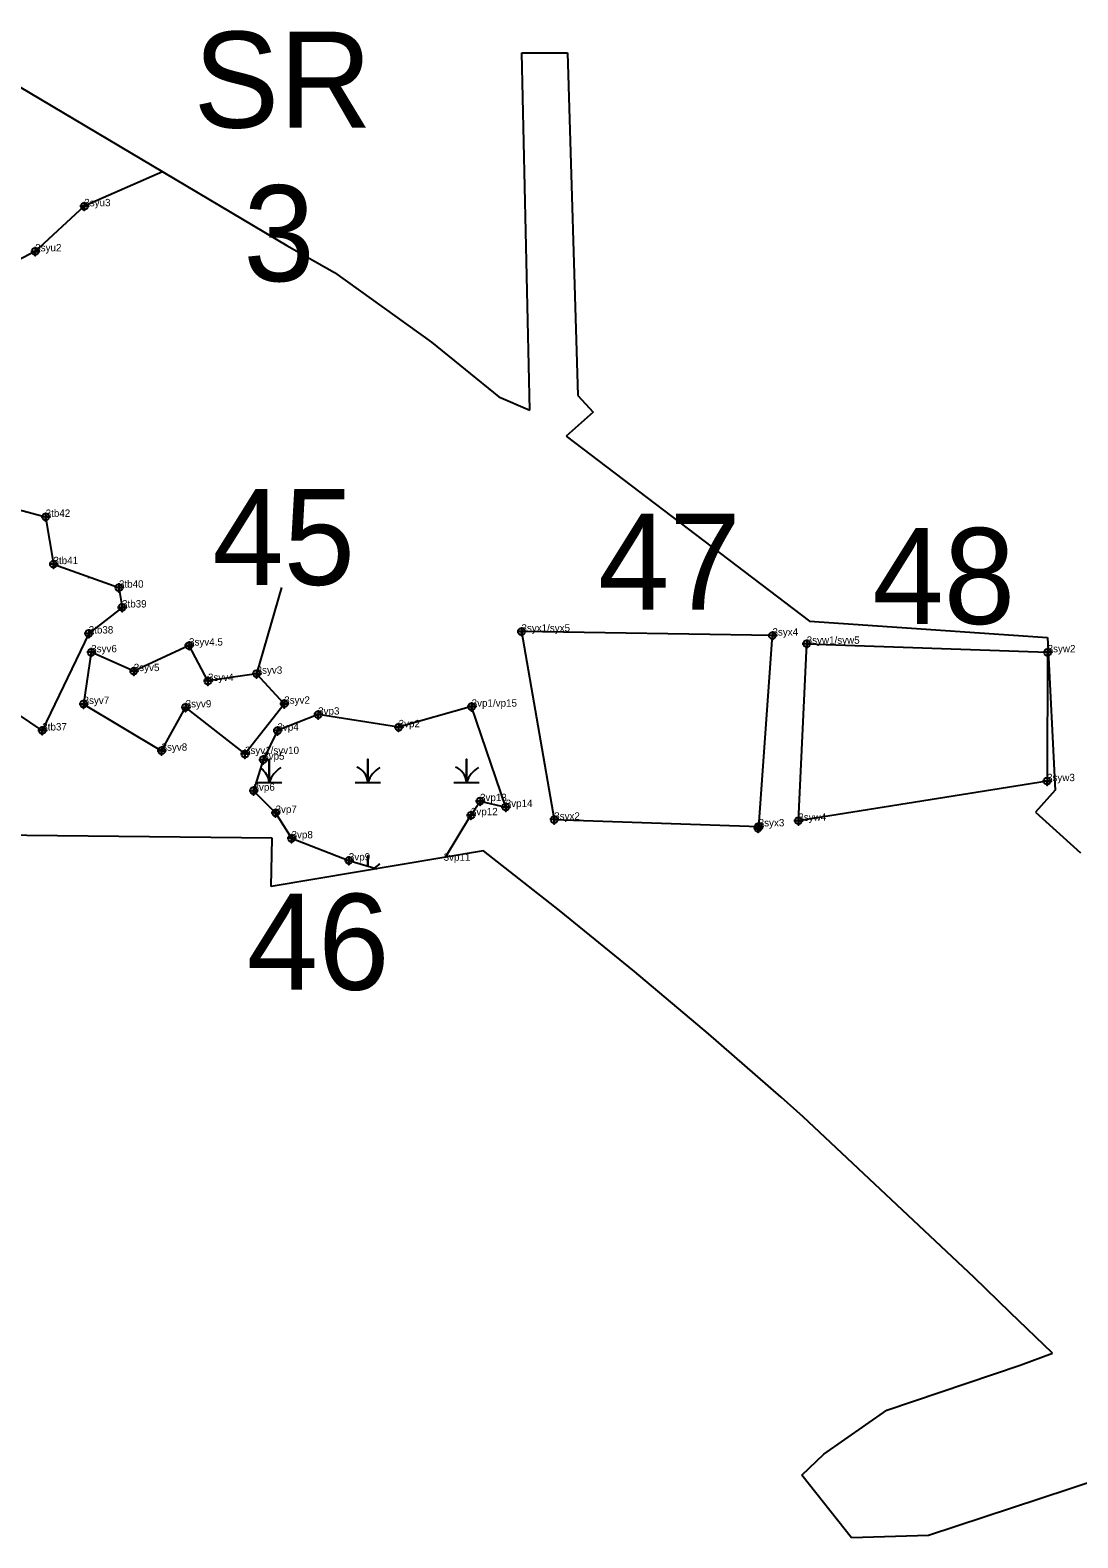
# Model space of a CAD drawing. Extents: x 2071991 to 2268989, y 436479 to 469629.
# Drawn here: x 2109076 to 2109789, y 454920 to 455947 of the extents above; entities that cross this region are included whole.
import ezdxf

# ---------------------------------------------------------------- set-up
doc = ezdxf.new("R2010")
doc.units = 0
for name, color, linetype in [('approx_PSA', 7, 'Continuous'), ('Default', 7, 'Continuous'), ('Exist Environmental Wetland Boundary', 7, 'Continuous'), ('Exist Environmental Wetland Boundary Cogo Comment', 7, 'Continuous'), ('Exist Environmental Wetland Boundary Cogo Point CELL', 7, 'Continuous'), ('Exist Hydro Jurisdictional Stream or Body of Water NEU Mitigable', 7, 'Continuous'), ('Exist Hydro Jurisdictional Stream or Body of Water NEU Mitigable Cogo Comment', 7, 'Continuous'), ('Exist Hydro Jurisdictional Stream or Body of Water NEU Mitigable Cogo Point CELL', 7, 'Continuous'), ('Exist Hydro Jurisdictional Stream or Body of Water NEU NonMitigable', 7, 'Continuous'), ('Exist Hydro Jurisdictional Stream or Body of Water NEU NonMitigable Cogo Comment', 7, 'Continuous'), ('Exist Hydro Jurisdictional Stream or Body of Water NEU NonMitigable Cogo Point CELL', 7, 'Continuous'), ('Exist Hydro Swamp or Marsh', 7, 'Continuous')]:
    doc.layers.add(name, color=color, linetype=linetype)

msp = doc.modelspace()

# ---------------------------------------------------------------- linework, layer by layer
at = {"layer": 'approx_PSA'}
for p, q in [((2109415.7, 455688), (2109410.3, 455931.3)), ((2109410.3, 455931.3), (2109441.4, 455931.3)), ((2109441.4, 455931.3), (2109448.3, 455697.9)), ((2109049.7, 455919.1), (2109250.2, 455800)), ((2109250.2, 455800), (2109282.8, 455781.7)), ((2109282.8, 455781.7), (2109348.8, 455734.4)), ((2109348.8, 455734.4), (2109394.7, 455697.1)), ((2109448.3, 455697.9), (2109458.8, 455686.6)), ((2109394.7, 455697.1), (2109415.7, 455688)), ((2109458.8, 455686.6), (2109440.4, 455670.3)), ((2109440.4, 455670.3), (2109606.1, 455544.3)), ((2109606.1, 455544.3), (2109768.1, 455533.3)), ((2109768.1, 455533.3), (2109773.3, 455429.3)), ((2109773.3, 455429.3), (2109760, 455414.3)), ((2109760, 455414.3), (2109790.7, 455386.8)), ((2109240.3, 455396.7), (2108999.5, 455399.4)), ((2109239.7, 455363.8), (2109240.3, 455396.7)), ((2109384.1, 455388.1), (2109239.7, 455363.8)), ((2109435.9, 455347.5), (2109384.1, 455388.1)), ((2109486.9, 455306), (2109435.9, 455347.5)), ((2109537.3, 455263.6), (2109486.9, 455306)), ((2109586.9, 455220.4), (2109537.3, 455263.6)), ((2109601.7, 455207), (2109586.9, 455220.4)), ((2109718.2, 455097.6), (2109601.7, 455207)), ((2109742.7, 455073.9), (2109718.2, 455097.6)), ((2109771.5, 455046.1), (2109742.7, 455073.9)), ((2109749.6, 455038), (2109771.5, 455046.1)), ((2109658.7, 455007.4), (2109749.6, 455038)), ((2109615.9, 454977.5), (2109658.7, 455007.4)), ((2109600.8, 454963.2), (2109615.9, 454977.5)), ((2109634.8, 454920.5), (2109600.8, 454963.2)), ((2109805.6, 454961.2), (2109762.9, 454947.1)), ((2109762.9, 454947.1), (2109687, 454922)), ((2109687, 454922), (2109634.8, 454920.5))]:
    msp.add_line(p, q, dxfattribs=at)
at = {"layer": 'Default'}
msp.add_line((2109246.6, 455567.3), (2109229.7, 455508.6), dxfattribs=at)
at = {"layer": 'Exist Environmental Wetland Boundary'}
for points in [[(2109058, 455622.8), (2109086.1, 455615.4), (2109091.4, 455583.2), (2109136, 455567.2), (2109138.1, 455553.7), (2109115.4, 455536), (2109083.8, 455470), (2109058.6, 455486.9)], [(2109358.4, 455383.8), (2109375.6, 455412.3), (2109381.8, 455421.9), (2109399.3, 455417.9), (2109376.1, 455486.2), (2109326.4, 455472.2), (2109271.6, 455480.8), (2109243.9, 455469.9), (2109234.2, 455450.1), (2109227.6, 455429), (2109242.6, 455413.9), (2109253.5, 455396.6), (2109292.5, 455381.5), (2109311.8, 455375.9)]]:
    msp.add_lwpolyline(points, dxfattribs=at)
at = {"layer": 'Exist Environmental Wetland Boundary Cogo Point CELL'}
for points in [[(2109086.1, 455618.4), (2109086.1, 455612.4), (2109086.1, 455615.4), (2109089.1, 455615.4), (2109083.1, 455615.4)], [(2109091.4, 455586.2), (2109091.4, 455580.2), (2109091.4, 455583.2), (2109094.4, 455583.2), (2109088.4, 455583.2)], [(2109136, 455570.2), (2109136, 455564.2), (2109136, 455567.2), (2109139, 455567.2), (2109133, 455567.2)], [(2109138.1, 455556.7), (2109138.1, 455550.7), (2109138.1, 455553.7), (2109141.1, 455553.7), (2109135.1, 455553.7)], [(2109115.4, 455539), (2109115.4, 455533), (2109115.4, 455536), (2109118.4, 455536), (2109112.4, 455536)], [(2109271.6, 455483.8), (2109271.6, 455477.8), (2109271.6, 455480.8), (2109274.6, 455480.8), (2109268.6, 455480.8)], [(2109376.1, 455489.2), (2109376.1, 455483.2), (2109376.1, 455486.2), (2109379.1, 455486.2), (2109373.1, 455486.2)], [(2109083.8, 455473), (2109083.8, 455467), (2109083.8, 455470), (2109086.8, 455470), (2109080.8, 455470)], [(2109243.9, 455472.9), (2109243.9, 455466.9), (2109243.9, 455469.9), (2109246.9, 455469.9), (2109240.9, 455469.9)], [(2109326.4, 455475.2), (2109326.4, 455469.2), (2109326.4, 455472.2), (2109329.4, 455472.2), (2109323.4, 455472.2)], [(2109234.2, 455453.1), (2109234.2, 455447.1), (2109234.2, 455450.1), (2109237.2, 455450.1), (2109231.2, 455450.1)], [(2109227.6, 455432), (2109227.6, 455426), (2109227.6, 455429), (2109230.6, 455429), (2109224.6, 455429)], [(2109381.8, 455424.9), (2109381.8, 455418.9), (2109381.8, 455421.9), (2109384.8, 455421.9), (2109378.8, 455421.9)], [(2109399.3, 455420.9), (2109399.3, 455414.9), (2109399.3, 455417.9), (2109402.3, 455417.9), (2109396.3, 455417.9)], [(2109242.6, 455416.9), (2109242.6, 455410.9), (2109242.6, 455413.9), (2109245.6, 455413.9), (2109239.6, 455413.9)], [(2109375.6, 455415.3), (2109375.6, 455409.3), (2109375.6, 455412.3), (2109378.6, 455412.3), (2109372.6, 455412.3)], [(2109253.5, 455399.6), (2109253.5, 455393.6), (2109253.5, 455396.6), (2109256.5, 455396.6), (2109250.5, 455396.6)], [(2109292.5, 455384.5), (2109292.5, 455378.5), (2109292.5, 455381.5), (2109295.5, 455381.5), (2109289.5, 455381.5)]]:
    msp.add_lwpolyline(points, dxfattribs=at)
for centre in [(2109086.1, 455615.4), (2109091.4, 455583.2), (2109136, 455567.2), (2109138.1, 455553.7), (2109115.4, 455536), (2109271.6, 455480.8), (2109376.1, 455486.2), (2109083.8, 455470), (2109243.9, 455469.9), (2109326.4, 455472.2), (2109234.2, 455450.1), (2109227.6, 455429), (2109381.8, 455421.9), (2109242.6, 455413.9), (2109375.6, 455412.3), (2109399.3, 455417.9), (2109253.5, 455396.6), (2109292.5, 455381.5)]:
    msp.add_circle(centre, 2.34, dxfattribs=at)
at = {"layer": 'Exist Hydro Jurisdictional Stream or Body of Water NEU Mitigable'}
msp.add_lwpolyline([(2109165.6, 455850.2), (2109112.4, 455826.8), (2109079, 455796.1), (2109030.1, 455771.3)], dxfattribs=at)
at = {"layer": 'Exist Hydro Jurisdictional Stream or Body of Water NEU Mitigable Cogo Point CELL'}
for points in [[(2109112.4, 455829.8), (2109112.4, 455823.8), (2109112.4, 455826.8), (2109115.4, 455826.8), (2109109.4, 455826.8)], [(2109079, 455799.1), (2109079, 455793.1), (2109079, 455796.1), (2109082, 455796.1), (2109076, 455796.1)]]:
    msp.add_lwpolyline(points, dxfattribs=at)
for centre in [(2109112.4, 455826.8), (2109079, 455796.1)]:
    msp.add_circle(centre, 2.34, dxfattribs=at)
at = {"layer": 'Exist Hydro Jurisdictional Stream or Body of Water NEU NonMitigable'}
for points in [[(2109410, 455537.3), (2109432.3, 455409.3), (2109571.5, 455404.7), (2109580.9, 455534.6)], [(2109221.8, 455454), (2109248.5, 455488.2), (2109229.7, 455508.6), (2109196.6, 455503.7), (2109183.7, 455527.8), (2109146.1, 455510.4), (2109117.1, 455523.2), (2109111.9, 455488), (2109165, 455456.2), (2109181.4, 455485.7)], [(2109604.2, 455529), (2109768.2, 455523.2), (2109767.8, 455435.5), (2109598.5, 455408.5)]]:
    msp.add_lwpolyline(points, close=True, dxfattribs=at)
at = {"layer": 'Exist Hydro Jurisdictional Stream or Body of Water NEU NonMitigable Cogo Point CELL'}
for points in [[(2109410, 455540.3), (2109410, 455534.3), (2109410, 455537.3), (2109413, 455537.3), (2109407, 455537.3)], [(2109580.9, 455537.6), (2109580.9, 455531.6), (2109580.9, 455534.6), (2109583.9, 455534.6), (2109577.9, 455534.6)], [(2109117.1, 455526.2), (2109117.1, 455520.2), (2109117.1, 455523.2), (2109120.1, 455523.2), (2109114.1, 455523.2)], [(2109183.7, 455530.8), (2109183.7, 455524.8), (2109183.7, 455527.8), (2109186.7, 455527.8), (2109180.7, 455527.8)], [(2109604.2, 455532), (2109604.2, 455526), (2109604.2, 455529), (2109607.2, 455529), (2109601.2, 455529)], [(2109768.2, 455526.2), (2109768.2, 455520.2), (2109768.2, 455523.2), (2109771.2, 455523.2), (2109765.2, 455523.2)], [(2109146.1, 455513.4), (2109146.1, 455507.4), (2109146.1, 455510.4), (2109149.1, 455510.4), (2109143.1, 455510.4)], [(2109196.6, 455506.7), (2109196.6, 455500.7), (2109196.6, 455503.7), (2109199.6, 455503.7), (2109193.6, 455503.7)], [(2109229.7, 455511.6), (2109229.7, 455505.6), (2109229.7, 455508.6), (2109232.7, 455508.6), (2109226.7, 455508.6)], [(2109111.9, 455491), (2109111.9, 455485), (2109111.9, 455488), (2109114.9, 455488), (2109108.9, 455488)], [(2109181.4, 455488.7), (2109181.4, 455482.7), (2109181.4, 455485.7), (2109184.4, 455485.7), (2109178.4, 455485.7)], [(2109248.5, 455491.2), (2109248.5, 455485.2), (2109248.5, 455488.2), (2109251.5, 455488.2), (2109245.5, 455488.2)], [(2109165, 455459.2), (2109165, 455453.2), (2109165, 455456.2), (2109168, 455456.2), (2109162, 455456.2)], [(2109221.8, 455457), (2109221.8, 455451), (2109221.8, 455454), (2109224.8, 455454), (2109218.8, 455454)], [(2109767.8, 455438.5), (2109767.8, 455432.5), (2109767.8, 455435.5), (2109770.8, 455435.5), (2109764.8, 455435.5)], [(2109432.3, 455412.3), (2109432.3, 455406.3), (2109432.3, 455409.3), (2109435.3, 455409.3), (2109429.3, 455409.3)], [(2109598.5, 455411.5), (2109598.5, 455405.5), (2109598.5, 455408.5), (2109601.5, 455408.5), (2109595.5, 455408.5)], [(2109571.1, 455406.5), (2109571.1, 455400.5), (2109571.1, 455403.5), (2109574.1, 455403.5), (2109568.1, 455403.5)], [(2109571.5, 455407.7), (2109571.5, 455401.7), (2109571.5, 455404.7), (2109574.5, 455404.7), (2109568.5, 455404.7)]]:
    msp.add_lwpolyline(points, dxfattribs=at)
for centre in [(2109410, 455537.3), (2109580.9, 455534.6), (2109117.1, 455523.2), (2109183.7, 455527.8), (2109604.2, 455529), (2109768.2, 455523.2), (2109146.1, 455510.4), (2109196.6, 455503.7), (2109229.7, 455508.6), (2109111.9, 455488), (2109181.4, 455485.7), (2109248.5, 455488.2), (2109165, 455456.2), (2109221.8, 455454), (2109767.8, 455435.5), (2109432.3, 455409.3), (2109598.5, 455408.5), (2109571.1, 455403.5), (2109571.5, 455404.7)]:
    msp.add_circle(centre, 2.34, dxfattribs=at)
at = {"layer": 'Exist Hydro Swamp or Marsh'}
msp.add_line((2109114.9, 455574.4), (2109116.1, 455574.4), dxfattribs=at)
for points in [[(2109229.6, 455434.6), (2109238.2, 455434.6), (2109238.2, 455450.4), (2109238.2, 455434.6), (2109246.8, 455434.6)], [(2109296.8, 455434.6), (2109305.4, 455434.6), (2109305.4, 455450.4), (2109305.4, 455434.6), (2109314, 455434.6)], [(2109364, 455434.6), (2109372.6, 455434.6), (2109372.6, 455450.4), (2109372.6, 455434.6), (2109381.2, 455434.6)], [(2109305.4, 455377.8), (2109305.4, 455384.6), (2109305.4, 455377.8)]]:
    msp.add_lwpolyline(points, dxfattribs=at)
for centre, radius, start, end in [((2109226, 455433.7), 12.3, 4.1403, 58.4062), ((2109256.5, 455428.6), 19.2, 122.1274, 161.6222), ((2109293.2, 455433.7), 12.3, 4.1403, 67.535), ((2109323.7, 455428.6), 19.2, 122.1274, 161.6222), ((2109360.4, 455433.7), 12.3, 4.1403, 67.535), ((2109390.9, 455428.6), 19.2, 122.1274, 161.6222), ((2109323.7, 455362.8), 19.2, 122.1274, 134.7584)]:
    msp.add_arc(centre, radius, start, end, dxfattribs=at)

# ---------------------------------------------------------------- texts
at = {"layer": 'Default'}
for s, height, p in [('SR', 65.34, (2109186.8, 455880.3)), ('3', 65.3, (2109220.7, 455775.8)), ('45', 65.34, (2109199.5, 455569.1)), ('47', 65.34, (2109462.1, 455552.3)), ('48', 65.34, (2109648.9, 455542.5)), ('46', 65.34, (2109223, 455293.5))]:
    msp.add_text(s, height=height, dxfattribs=at).set_placement(p)
at = {"layer": 'Exist Environmental Wetland Boundary Cogo Comment'}
for s, p in [('3tb42', (2109086.1, 455615.4)), ('3tb41', (2109091.4, 455583.2)), ('3tb40', (2109136, 455567.2)), ('3tb39', (2109138.1, 455553.7)), ('3tb38', (2109115.4, 455536)), ('3vp3', (2109271.6, 455480.8)), ('3vp1/vp15', (2109376.1, 455486.2)), ('3tb37', (2109083.8, 455470)), ('3vp4', (2109243.9, 455469.9)), ('3vp2', (2109326.4, 455472.2)), ('3vp5', (2109234.2, 455450.1)), ('3vp6', (2109227.6, 455429)), ('3vp13', (2109381.8, 455421.9)), ('3vp14', (2109399.3, 455417.9)), ('3vp7', (2109242.6, 455413.9)), ('3vp12', (2109375.6, 455412.3)), ('3vp8', (2109253.5, 455396.6)), ('3vp9', (2109292.5, 455381.5)), ('3vp11', (2109357, 455381.3))]:
    msp.add_text(s, height=5, dxfattribs=at).set_placement(p)
at = {"layer": 'Exist Hydro Jurisdictional Stream or Body of Water NEU Mitigable Cogo Comment'}
for s, p in [('3syu3', (2109112.4, 455826.8)), ('3syu2', (2109079, 455796.1))]:
    msp.add_text(s, height=5, dxfattribs=at).set_placement(p)
at = {"layer": 'Exist Hydro Jurisdictional Stream or Body of Water NEU NonMitigable Cogo Comment'}
for s, p in [('3syx1/syx5', (2109410, 455537.3)), ('3syx4', (2109580.9, 455534.6)), ('3syw1/syw5', (2109604.2, 455529)), ('3syv6', (2109117.1, 455523.2)), ('3syv4.5', (2109183.7, 455527.8)), ('3syw2', (2109768.2, 455523.2)), ('3syv5', (2109146.1, 455510.4)), ('3syv3', (2109229.7, 455508.6)), ('3syv4', (2109196.6, 455503.7)), ('3syv7', (2109111.9, 455488)), ('3syv2', (2109248.5, 455488.2)), ('3syv9', (2109181.4, 455485.7)), ('3syv8', (2109165, 455456.2)), ('3syv1/syv10', (2109221.8, 455454)), ('3syw3', (2109767.8, 455435.5)), ('3syx2', (2109432.3, 455409.3)), ('3syw4', (2109598.5, 455408.5)), ('3syx3', (2109571.5, 455404.7))]:
    msp.add_text(s, height=5, dxfattribs=at).set_placement(p)

doc.saveas('drawing.dxf')
